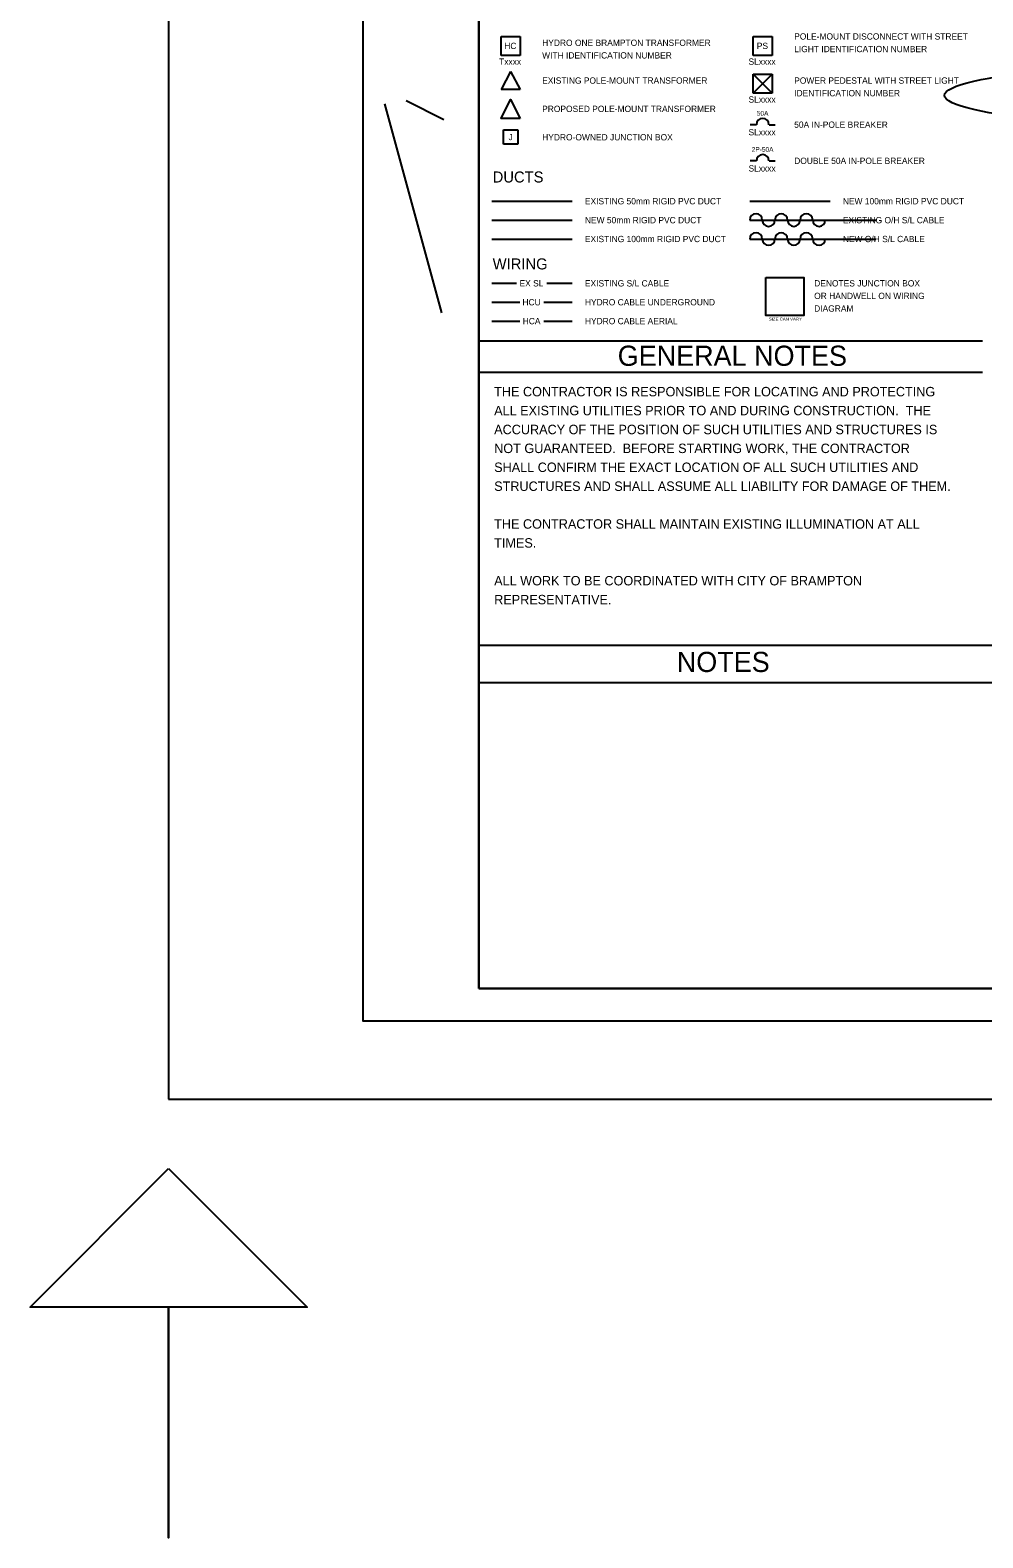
# Model space of a CAD drawing. Extents: x 602909 to 603631, y 4846273 to 4846729.
# Drawn here: x 602908.8 to 603054.8, y 4846273.4 to 4846504.5 of the extents above; entities that cross this region are included whole.
import ezdxf

# ---------------------------------------------------------------- set-up
doc = ezdxf.new("R2010")
doc.units = 0
for name, color, linetype in [('-PRINT FULLSIZE', 7, 'Continuous'), ('-PRINT HALFSIZE', 7, 'Continuous'), ('ENG_BORDER', 7, 'Continuous'), ('ENG_TX_TITLEBLOCK', 7, 'Continuous'), ('ENG_WK_MISC-1', 7, 'Continuous'), ('SL - Border Text', 7, 'Continuous'), ('STL_CONDUCTORS_OH', 7, 'Continuous'), ('STL_CONDUIT_UG_100mm', 7, 'Continuous'), ('STL_CONDUIT_UG_50mm', 7, 'Continuous'), ('STL_EXIST_CONDUIT_UG_100mm', 7, 'Continuous'), ('STL_EXIST_CONDUIT_UG_50mm', 7, 'Continuous'), ('STL_EXISTING_CONDUCTORS_OH', 7, 'Continuous'), ('STL_EXISTING_TRANSFORMERS', 7, 'Continuous'), ('STL_ID', 7, 'Continuous'), ('STL_POWER_SUPPLY', 7, 'Continuous'), ('STL_TRANSFORMERS', 7, 'Continuous'), ('STL_WIRING', 7, 'Continuous')]:
    doc.layers.add(name, color=color, linetype=linetype)

msp = doc.modelspace()

# ---------------------------------------------------------------- linework, layer by layer
at = {"layer": '-PRINT FULLSIZE'}
msp.add_lwpolyline([(602930, 4846340.65), (603377.03, 4846340.65), (603377.03, 4846645.65), (602930, 4846645.65)], close=True, dxfattribs=at)
at = {"layer": '-PRINT HALFSIZE'}
msp.add_lwpolyline([(602959.8, 4846631.64), (603368.72, 4846631.64), (603368.72, 4846352.64), (602959.8, 4846352.64)], close=True, dxfattribs=at)
at = {"layer": 'ENG_BORDER'}
for p, q in [((602977.52, 4846357.64), (602977.52, 4846626.85)), ((602977.52, 4846456.89), (603054.73, 4846456.89)), ((602977.52, 4846452.07), (603054.73, 4846452.07)), ((602977.52, 4846410.23), (603363.74, 4846410.23)), ((602977.52, 4846404.5), (603194.76, 4846404.5)), ((603363.72, 4846357.64), (602977.52, 4846357.64))]:
    msp.add_line(p, q, dxfattribs=at)
msp.add_lwpolyline([(602977.52, 4846357.64), (603363.72, 4846357.64), (603363.72, 4846626.64), (602977.52, 4846626.64)], close=True, dxfattribs=at)
at = {"layer": 'ENG_WK_MISC-1'}
msp.add_lwpolyline([(602930, 4846330.02), (602951.22, 4846308.8), (602930, 4846308.8), (602930, 4846273.45), (602930, 4846308.8), (602908.79, 4846308.8)], close=True, dxfattribs=at)
at = {"layer": 'SL - Border Text'}
for p, q in [((602963.09, 4846493.16), (602971.84, 4846461.16)), ((602966.42, 4846493.68), (602972.18, 4846490.8)), ((603019.04, 4846475.37), (603038.35, 4846475.37)), ((603019.04, 4846472.47), (603038.35, 4846472.47))]:
    msp.add_line(p, q, dxfattribs=at)
at = {"layer": 'STL_CONDUCTORS_OH'}
for centre, start, end in [((603020.01, 4846472.47), 0, 180), ((603023.87, 4846472.47), 0, 180), ((603027.73, 4846472.47), 0, 180), ((603021.94, 4846472.47), 180, 0), ((603025.8, 4846472.47), 180, 0), ((603029.66, 4846472.47), 180, 0)]:
    msp.add_arc(centre, 0.965, start, end, dxfattribs=at)
at = {"layer": 'STL_CONDUIT_UG_100mm'}
msp.add_line((603019.04, 4846478.26), (603031.38, 4846478.26), dxfattribs=at)
at = {"layer": 'STL_CONDUIT_UG_50mm'}
msp.add_line((602979.52, 4846475.37), (602991.85, 4846475.37), dxfattribs=at)
at = {"layer": 'STL_EXIST_CONDUIT_UG_100mm'}
msp.add_line((602979.52, 4846472.47), (602991.85, 4846472.47), dxfattribs=at)
at = {"layer": 'STL_EXIST_CONDUIT_UG_50mm'}
msp.add_line((602979.52, 4846478.26), (602991.85, 4846478.26), dxfattribs=at)
at = {"layer": 'STL_EXISTING_CONDUCTORS_OH'}
for centre, start, end in [((603020.01, 4846475.37), 0, 180), ((603023.87, 4846475.37), 0, 180), ((603027.73, 4846475.37), 0, 180), ((603021.94, 4846475.37), 180, 0), ((603025.8, 4846475.37), 180, 0), ((603029.66, 4846475.37), 180, 0)]:
    msp.add_arc(centre, 0.965, start, end, dxfattribs=at)
at = {"layer": 'STL_EXISTING_TRANSFORMERS'}
for p, q in [((602980.97, 4846500.61), (602980.97, 4846503.51)), ((602980.97, 4846503.51), (602983.86, 4846503.51)), ((602982.41, 4846503.51), (602983.86, 4846503.51)), ((602983.86, 4846503.51), (602983.86, 4846500.61)), ((602983.86, 4846500.61), (602980.97, 4846500.61)), ((602982.41, 4846498.12), (602980.97, 4846495.38)), ((602982.41, 4846498.12), (602983.86, 4846495.38)), ((602983.86, 4846495.38), (602980.97, 4846495.38)), ((602981.33, 4846487.01), (602981.33, 4846489.18)), ((602981.33, 4846489.18), (602983.5, 4846489.18)), ((602983.5, 4846489.18), (602983.5, 4846487.01)), ((602983.5, 4846487.01), (602981.33, 4846487.01))]:
    msp.add_line(p, q, dxfattribs=at)
at = {"layer": 'STL_ID'}
msp.add_ellipse((603105.77, 4846494.48), major_axis=(56.88, 0), ratio=0.097916, dxfattribs=at)
at = {"layer": 'STL_POWER_SUPPLY'}
for p, q in [((603019.59, 4846500.61), (603019.59, 4846503.51)), ((603019.59, 4846503.51), (603022.48, 4846503.51)), ((603021.03, 4846503.51), (603022.48, 4846503.51)), ((603022.48, 4846503.51), (603022.48, 4846500.61)), ((603022.48, 4846500.61), (603019.59, 4846500.61)), ((603019.59, 4846494.82), (603019.59, 4846497.72)), ((603019.59, 4846497.72), (603022.48, 4846497.72)), ((603019.59, 4846497.72), (603022.48, 4846494.82)), ((603022.48, 4846497.72), (603019.59, 4846494.82)), ((603021.03, 4846497.72), (603022.48, 4846497.72)), ((603022.48, 4846497.72), (603022.48, 4846494.82)), ((603022.48, 4846494.82), (603019.59, 4846494.82)), ((603020.07, 4846489.99), (603019.1, 4846489.99)), ((603022, 4846489.99), (603022.96, 4846489.99)), ((603020.07, 4846484.45), (603019.1, 4846484.45)), ((603022, 4846484.45), (603022.96, 4846484.45))]:
    msp.add_line(p, q, dxfattribs=at)
for centre in [(603021.03, 4846489.99), (603021.03, 4846484.45)]:
    msp.add_arc(centre, 0.965, 0, 180, dxfattribs=at)
at = {"layer": 'STL_TRANSFORMERS'}
msp.add_lwpolyline([(602983.86, 4846490.96), (602980.97, 4846490.96), (602982.41, 4846493.86), (602982.41, 4846493.86)], close=True, dxfattribs=at)
at = {"layer": 'STL_WIRING'}
for p, q in [((602979.52, 4846465.68), (602983.31, 4846465.68)), ((602987.94, 4846465.68), (602991.85, 4846465.68)), ((602979.52, 4846462.78), (602983.81, 4846462.78)), ((602987.49, 4846462.78), (602991.85, 4846462.78)), ((602979.52, 4846459.89), (602983.82, 4846459.89)), ((602987.48, 4846459.89), (602991.85, 4846459.89))]:
    msp.add_line(p, q, dxfattribs=at)
msp.add_lwpolyline([(603021.53, 4846466.56), (603027.32, 4846466.56), (603027.32, 4846460.76), (603021.53, 4846460.76)], close=True, dxfattribs=at)

# ---------------------------------------------------------------- texts
at = {"layer": 'ENG_TX_TITLEBLOCK'}
for s, height, rotation, p in [('POLE-MOUNT DISCONNECT WITH STREET ', 0.9655, 359.9999, (603025.86, 4846503.03)), ('WITH IDENTIFICATION NUMBER', 0.9655, 359.9999, (602987.24, 4846500.13)), ('HYDRO ONE BRAMPTON TRANSFORMER ', 0.9655, 359.9999, (602987.24, 4846502.06)), ('LIGHT IDENTIFICATION NUMBER', 0.9655, 359.9999, (603025.86, 4846501.1)), ('EXISTING POLE-MOUNT TRANSFORMER', 0.9655, 359.9999, (602987.24, 4846496.27)), ('POWER PEDESTAL WITH STREET LIGHT ', 0.9655, 359.9999, (603025.86, 4846496.27)), ('IDENTIFICATION NUMBER', 0.9655, 359.9999, (603025.86, 4846494.34)), ('PROPOSED POLE-MOUNT TRANSFORMER', 0.9655, 359.9999, (602987.24, 4846491.93)), ('50A IN-POLE BREAKER', 0.9655, 359.9999, (603025.86, 4846489.51)), ('HYDRO-OWNED JUNCTION BOX', 0.9655, 359.9999, (602987.24, 4846487.58)), ('DOUBLE 50A IN-POLE BREAKER', 0.9655, 359.9999, (603025.86, 4846483.97)), ('DUCTS', 1.69, 360, (602979.66, 4846481.13)), ('EXISTING 50mm RIGID PVC DUCT', 0.9655, 359.9999, (602993.79, 4846477.78)), ('NEW 100mm RIGID PVC DUCT', 0.9655, 359.9999, (603033.31, 4846477.78)), ('NEW 50mm RIGID PVC DUCT', 0.9655, 359.9999, (602993.79, 4846474.88)), ('EXISTING O/H S/L CABLE', 0.9655, 359.9999, (603033.31, 4846474.88)), ('EXISTING 100mm RIGID PVC DUCT', 0.9655, 359.9999, (602993.79, 4846471.99)), ('NEW O/H S/L CABLE', 0.9655, 359.9999, (603033.31, 4846471.99)), ('WIRING', 1.69, 360, (602979.66, 4846467.81)), ('EXISTING S/L CABLE', 0.9655, 359.9999, (602993.79, 4846465.2)), ('OR HANDWELL ON WIRING ', 0.9655, 359.9999, (603028.92, 4846463.27)), ('DENOTES JUNCTION BOX', 0.9655, 359.9999, (603028.92, 4846465.2)), ('HYDRO CABLE UNDERGROUND', 0.9655, 359.9999, (602993.79, 4846462.3)), ('DIAGRAM', 0.965, 359.9999, (603028.92, 4846461.34)), ('HYDRO CABLE AERIAL', 0.9655, 359.9999, (602993.79, 4846459.41)), ('NOTES', 3.09, 360, (603007.87, 4846406.12))]:
    msp.add_text(s, height=height, rotation=rotation, dxfattribs=at).set_placement(p)
for s, height, p in [('THE CONTRACTOR IS RESPONSIBLE FOR LOCATING AND PROTECTING', 1.4482, (602979.89, 4846448.36)), ('ALL EXISTING UTILITIES PRIOR TO AND DURING CONSTRUCTION.  THE ', 1.4482, (602979.89, 4846445.46)), ('ACCURACY OF THE POSITION OF SUCH UTILITIES AND STRUCTURES IS ', 1.4482, (602979.89, 4846442.56)), ('NOT GUARANTEED.  BEFORE STARTING WORK, THE CONTRACTOR ', 1.4482, (602979.89, 4846439.67)), ('SHALL CONFIRM THE EXACT LOCATION OF ALL SUCH UTILITIES AND ', 1.4482, (602979.89, 4846436.77)), ('STRUCTURES AND SHALL ASSUME ALL LIABILITY FOR DAMAGE OF THEM.   ', 1.4482, (602979.89, 4846433.87)), ('THE CONTRACTOR SHALL MAINTAIN EXISTING ILLUMINATION AT ALL ', 1.4482, (602979.89, 4846428.08)), ('TIMES.', 1.448, (602979.89, 4846425.18)), ('ALL WORK TO BE COORDINATED WITH CITY OF BRAMPTON ', 1.4482, (602979.89, 4846419.39)), ('REPRESENTATIVE.', 1.4482, (602979.89, 4846416.49))]:
    msp.add_text(s, height=height, dxfattribs=at).set_placement(p)
at = {"layer": 'SL - Border Text'}
for s, height, rotation, p in [('SIZE CAN VARY', 0.4827, 359.9999, (603021.97, 4846459.96)), ('GENERAL NOTES', 3.0896, 360, (602998.82, 4846453.04))]:
    msp.add_text(s, height=height, rotation=rotation, dxfattribs=at).set_placement(p)
at = {"layer": 'STL_EXISTING_TRANSFORMERS'}
for s, p in [('HC', (602981.44, 4846501.58)), ('Txxxx', (602980.65, 4846499.17)), ('J', (602982.08, 4846487.62))]:
    msp.add_text(s, height=0.965, rotation=359.9999, dxfattribs=at).set_placement(p)
at = {"layer": 'STL_POWER_SUPPLY'}
for s, p in [('PS', (603020.13, 4846501.58)), ('SLxxxx', (603018.86, 4846499.17)), ('SLxxxx', (603018.86, 4846493.37)), ('SLxxxx', (603018.86, 4846488.35)), ('SLxxxx', (603018.86, 4846482.81))]:
    msp.add_text(s, height=0.965, rotation=359.9999, dxfattribs=at).set_placement(p)
for s, p in [('50A', (603020.13, 4846491.37)), ('2P-50A', (603019.35, 4846485.83))]:
    msp.add_text(s, height=0.724, dxfattribs=at).set_placement(p)
at = {"layer": 'STL_WIRING'}
for s, p in [('EX SL', (602983.77, 4846465.2)), ('HCU', (602984.22, 4846462.3)), ('HCA', (602984.26, 4846459.41))]:
    msp.add_text(s, height=0.965, dxfattribs=at).set_placement(p)

doc.saveas('drawing.dxf')
